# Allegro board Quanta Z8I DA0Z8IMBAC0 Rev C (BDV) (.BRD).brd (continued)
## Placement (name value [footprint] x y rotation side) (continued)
PR7100  4.75K_1%_4  [R0402]  160.57 149.01 180 top
PR7101  4.7K_NTC_4_1%  [R0402]  136.88 169.52 0 bottom
PR7102  *Short_0402  [S0402]  169.66 149.11 180 top
PR7103  *10K_1%_4  [R0402]  160.27 143.6 0 top
PR7104  10K_1%_4  [R0402]  161.16 142.56 0 top
PR7105  *Short_0402  [S0402]  150.9 159.49 180 bottom
PR7106  1_5%_6  [R0603]  156.72 158.4 90 bottom
PR7107  *Short_0402  [S0402]  155.19 161.53 0 bottom
PR7108  2.2_1%_6  [R0603]  152.99 161.75 0 bottom
PR7109  *Short_0402  [S0402]  155.78 167.52 180 bottom
PR7110  1_5%_6  [R0603]  149.61 166.96 0 bottom
PR7111  *Short_0402  [S0402]  153.78 164.1 0 bottom
PR7112  2.2_1%_6  [R0603]  155.67 162.75 180 bottom
PR7113  *Short_0402  [S0402]  163.29 133.06 90 top
PR7114  1_5%_6  [R0603]  164.85 129.92 0 bottom
PR7115  *Short_0402  [S0402]  167.42 129.57 0 top
PR7116  2.2_1%_6  [R0603]  162.72 130.86 90 top
PR8000  100K_1%_4  [R0402]  30.53 103.07 270 top
PR8001  20K_1%_2  [R0201]  52.61 200.28 180 top
PR8002  220K_1%_4  [R0402]  56.47 196.9 0 top
PR8003  20K_1%_2  [R0201]  32.46 102 180 top
PR8004  220K_1%_4  [R0402]  35.56 101.6 270 top
PR8005  10K_1%_2  [R0201]  52.96 198.8 270 top
PR8006  200K_1%_4  [R0402]  34.11 97.29 90 top
PR8007  10K_1%_2  [R0201]  34.19 102 0 top
PR8008  220K_1%_4  [R0402]  54.71 196.9 0 top
PR8009  110K_1%_4  [R0402]  36.75 101.61 90 top
PR8010  *Short_0402  [S0402]  51.06 196.67 180 top
PR8011  *0_5%_4  [R0402]  52.84 197.35 0 top
PR8012  100K_1%_4  [R0402]  48.31 199.06 90 top
PR8013  *Short_0402  [S0402]  48.29 197.33 270 top
PR8014  *Short_0402  [S0402]  32.73 97.66 180 top
PR8015  *Short_0402  [S0402]  39.48 100.3 90 top
PR8016  300K_1%_4  [R0402]  35.17 97.33 90 top
PR8017  100K_1%_4  [R0402]  38.49 100.33 270 top
PR8018  549K_1%_4  [R0402]  56.49 195.91 0 top
PR8019  *0_5%_4  [R0402]  54.74 195.91 180 top
PR8020  *Short_0402  [S0402]  53.01 195.91 0 top
PR8021  76.8K_1%_4  [R0402]  56.85 194.56 90 top
PR8022  47K_1%_4  [R0402]  25.4 103.2 270 top
PR8023  470K_5%_4  [R0402]  82.58 187.32 0 top
PR8024  47K_1%_4  [R0402]  88.72 190.49 180 top
PR8025  *1M_5%_4  [R0402]  58.83 192.86 270 top
PR8026  *Short_0402  [S0402]  57.84 192.86 90 top
PR8027  33K_1%_4  [R0402]  57.86 194.61 270 top
PR8028  220K_5%_4  [R0402]  50.7 191.59 0 top
PR8029  100K_1%_4  [R0402]  56.82 192.83 90 top
PR8030  100K_1%_4  [R0402]  83.23 190.31 90 top
PR8031  470K_5%_4  [R0402]  26.44 103.2 270 top
PR8032  470K_5%_4  [R0402]  88.72 189.5 180 top
PR8033  *Short_0402  [S0402]  24.36 116.76 90 top
PR8034  *Short_0402  [S0402]  16.84 113.9 90 top
PR8035  10K_1%_2  [R0201]  24.01 118.08 180 top
PR8036  18.7K_1%_4  [R0402]  16.48 117.34 90 top
PR8037  *0_5%_4  [R0402]  17.86 113.88 90 top
PR8038  *10K_1%_2  [R0201]  31.27 116.56 90 top
PR8039  10K_1%_4  [R0402]  17.62 118.59 270 top
PR8040  10K_1%_2  [R0201]  23.02 118.08 0 top
PR8041  *Short_0402  [S0402]  31.02 114.83 0 top
PR8042  1M_1%_2  [R0201]  25.67 113.8 0 top
PR8043  1M_1%_2  [R0201]  31.27 117.57 90 top
PR8044  510K_5%_2  [R0201]  22.33 115.47 270 top
PR8045  220K_5%_2  [R0201]  24.31 112.54 180 top
PR8046  1K_1%_2  [R0201]  25.53 115.9 90 top
PR8047  220K_5%_2  [R0201]  25.5 112.57 0 top
PR8048  *1K_1%_2  [R0201]  25.53 114.88 270 top
PR8049  *Short_0402  [S0402]  28.42 106.43 90 top
PR8050  *0_5%_4  [R0402]  30.23 106.03 90 top
PR8051  *Short_0402  [S0402]  30.87 107.39 0 top
PR8052  *Short_0402  [S0402]  35.74 114.35 180 top
PR8053  27.4K_1%_4  [R0402]  31.64 109.92 90 top
PR8054  10K_1%_2  [R0201]  33.38 114.2 0 top
PR8055  10.2K_1%_4  [R0402]  32.64 108.49 270 top
PR8056  1M_1%_2  [R0201]  24.49 111.55 90 top
PR8057  10K_1%_2  [R0201]  34.37 114.2 0 top
PR8058  *10K_1%_2  [R0201]  19.36 111.99 270 top
PR8059  1M_1%_2  [R0201]  27.03 108.56 270 top
PR8060  *Short_0402  [S0402]  18.06 111.96 180 top
PR8061  220K_5%_2  [R0201]  27.48 111.97 270 top
PR8062  220K_5%_2  [R0201]  24.49 110.54 270 top
PR8063  1K_1%_2  [R0201]  24.34 109.52 180 top
PR8064  1M_1%_2  [R0201]  19.36 110.99 270 top
PR9000  EV@1_5%_6  [R0603]  95.89 192.15 270 top
PR9001  EV@1_5%_6  [R0603]  105.08 200.05 135 top
PR9002  EV@499K_1%_4  [R0402]  98.17 194 0 top
PR9004  *EV@2.2_5%_6  [R0603]  105.11 202.92 315 bottom
PR9006  EV@1_5%_6  [R0603]  97.79 199.06 0 bottom
PR9008  *Short_0201  [S0201]  104.45 194.1 180 top
PR9009  EV@10K_1%_2  [R0201]  104.45 193.39 180 top
PR9011  EV@14.7K_1%_4  [R0402]  101.94 198.05 45 bottom
PR9013  EV@10K_1%_4  [R0402]  104.35 193.49 270 bottom
PR9014  EV@1_5%_6  [R0603]  113.59 191.59 90 bottom
PR9015  *Short_0201  [S0201]  96.93 197.41 0 top
PR9016  *Short_0402  [S0402]  96.59 198.99 180 top
PR9017  *Short_0201  [S0201]  97.86 197.52 270 top
PR9018  *EV@12K_1%_4  [R0402]  96.59 199.96 180 top
PR9019  *EV@2.2_5%_6  [R0603]  105.46 196.29 270 bottom
PR9021  EV@20.5K_1%_4  [R0402]  97.59 195.98 270 bottom
PR9022  *EV@10K_1%_4  [R0402]  98.02 198.88 90 top
PR9023  EV@6.19K_1%_4  [R0402]  97.36 196.55 180 top
PR9024  EV@4.32K_1%_4  [R0402]  95.63 196.57 0 top
PR9025  *EV@0_5%_2  [R0201]  102.16 193.95 45 bottom
PR9026  EV@100_1%_4  [R0402]  115.25 188.66 180 bottom
PR9027  EV@16.5K_1%_4  [R0402]  94.69 195.45 0 top
PR9028  *Short_0201  [S0201]  99.1 191.48 180 top
PR9029  *Short_0201  [S0201]  99.1 192.19 180 top
PR9030  EV@309_1%_4  [R0402]  93.35 195.84 90 top
PR9031  EV@100_1%_4  [R0402]  116.29 190.31 90 bottom
PR9032  EV@14.7K_1%_4  [R0402]  99.77 194.76 135 bottom
PR9033  EV@10K_1%_2  [R0201]  102.92 192.76 315 top
PR9034  *Short_0201  [S0201]  102.67 197.51 225 bottom
PR9067  *Short_0805  [S0805]  97.06 186.08 90 bottom
PR9068  *Short_0805  [S0805]  96.15 183.41 180 bottom
PR9069  *Short_0402  [S0402]  88.95 184.17 180 top
PR9070  *Short_0201  [S0201]  88.95 183.16 180 top
PR9072  *Short_0201  [S0201]  88.95 185.19 0 top
PR9073  EV@5.6_5%_8  [R0805]  95.05 192 180 bottom
PR9074  EV@100K_1%_4  [R0402]  104.42 191.54 90 bottom
PR9075  EV@10K_1%_4  [R0402]  104.04 187.87 0 bottom
PR9076  EV@10K_1%_2  [R0201]  105.85 183.79 0 bottom
PR9077  EV@1M_5%_4  [R0402]  103.46 191.54 270 bottom
PR9078  *Short_0201  [S0201]  104.7 183.79 180 bottom
PR9079  *Short_0201  [S0201]  98.69 180.99 0 bottom
PR9080  EV@47_1%_4  [R0402]  100.59 186.7 180 bottom
PR9081  EV@133_1%_4  [R0402]  99.24 186.97 90 bottom
PR9082  EV@124_1%_4  [R0402]  98.81 184.63 270 bottom
PR9085  *Short_0402  [S0402]  100 197.08 270 bottom
PR9086  EV@100K_1%_4  [R0402]  168.06 151.32 0 bottom
PR9087  EV@10_5%_6  [R0603]  167.54 158.17 0 bottom
PR9088  EV@100K_1%_2  [R0201]  167.87 157.94 180 top
PR9089  EV@2.2_5%_6  [R0603]  165.51 158.81 90 bottom
PR9090  *Short_0201  [S0201]  167.66 155.99 270 top
PR9091  *EV@0_5%_2  [R0201]  168.46 156.62 90 top
PR9092  *EV@4.7_5%_6  [R0603]  161.79 158.29 180 top
PR9093  EV@0_5%_2  [R0201]  168.71 155.75 180 top
PR9094  EV@6.49K_1%_4  [R0402]  170.41 151.3 270 bottom
PR9095  EV@2.2K_5%_4  [R0402]  168.91 155.3 180 bottom
PR9096  *EV@0_5%_4  [R0402]  169.79 153.09 0 bottom
PR9097  EV@9.31K_1%_4  [R0402]  168.44 152.7 270 bottom
PR9098  *Short_0402  [S0402]  169.78 153.08 180 top
PR9099  EV@22_5%_8  [R0805]  165.32 168.16 90 top
PR9100  EV@100K_1%_4  [R0402]  160.1 168.55 180 top
PR9101  EV@1M_5%_4  [R0402]  160.48 167.1 90 top
PR9102  EV@1M_5%_6  [R0603]  154.65 168.25 180 top
PR9103  EV@22_5%_8  [R0805]  164.14 209.6 180 top
PR9104  EV@1M_5%_6  [R0603]  155.41 170.35 270 top
PR9105  *EV@100K_1%_6  [R0603]  158.46 209.94 90 top
PR9227  22_5%_8  [R0805]  36.88 125.12 0 top
PR9244  *Short_0805  [S0805]  205.65 126.2 0 bottom
PR9245  *Short_0805  [S0805]  209.17 129.34 180 bottom
PR9248  *Short_0805  [S0805]  37.02 158.86 270 top
PR9249  *Short_0805  [S0805]  32.19 159.41 0 top
PR9255  100K_1%_2  [R0201]  37.52 145.64 270 top
PR9256  *Short_0201  [S0201]  36.5 145.56 270 top
PR9258  *Short_0201  [S0201]  135.65 130.91 90 bottom
PR9259  *Short_0201  [S0201]  136.51 126.47 180 top
PR9263  *Short_0201  [S0201]  166.84 167 90 top
PR9268  *0_5%_2  [R0201]  169.95 132.25 270 bottom
PR9269  0_5%_2  [R0201]  169.19 132.25 270 bottom
PR9270  *0_5%_2  [R0201]  60.33 182.8 90 bottom
PR9271  0_5%_2  [R0201]  61.65 187.09 180 bottom
PR9272  *0_5%_2  [R0201]  136.36 130.91 270 bottom
PR9274  *100K_NTC_4_1%  [R0402]  107.04 202.46 90 bottom
PR9275  *Short_0201  [S0201]  162.79 121.33 90 top
PR9276  *Short_0201  [S0201]  160.07 123.03 180 top
PR9277  *Short_0402  [S0402]  38.87 101.7 180 top
PR9278  *Short_0402  [S0402]  83.8 188.85 0 top
PR9279  *Short_0402  [S0402]  29.29 104.67 0 top
PR9280  *Short_0402  [S0402]  68.91 205.25 270 top
PR9281  *Short_0402  [S0402]  25.87 101.82 0 top
PU1  BQ24780SRUYR  [QFN28-4X4-4-38P]  158.29 119.35 0 bottom
PU16  G5335QT2U  [QFN23-4X4-5-25P]  143.94 125.4 270 bottom
PU3002  TMP708AIDBVR  [SOT23-2_8-95-5P-LP2985-50DBVT]  132.28 113.98 0 bottom
PU3003  JW5222RSOTB_TRPBF  [SOT23-2_8-95-6P-1_1H]  5.29 34.64 0 bottom
PU3004  JW5213DFND_TRPBF  [DFN8-2X2-5-9P-MAX8902B]  36.25 140.74 180 top
PU5000  TPS51486RJER  [QFN18-3X3-5]  73.66 183.26 180 bottom
PU6000  RT6256BGQUF  [QFN12-3X3-45-0_6H]  176.71 130.65 0 bottom
PU6001  AOZ1331ADI  [DFN14-3X2-4-15P-0_85H]  200.63 128.93 90 bottom
PU6002  AOZ1331ADI  [DFN14-3X2-4-15P-0_85H]  34.98 163.34 180 top
PU6003  RT6258CGQUF  [QFN12-3X3-45-0_6H]  55.17 183.08 180 bottom
PU7000  RT3602AJGQW  [QFN48-6X6-4-49P-EXC7900-SG11]  164.1 142.81 180 bottom
PU7001  RT9610CGQW  [DFN8-2X2-5-9P]  154.59 144.01 270 bottom
PU7002  RT9610CGQW  [DFN8-2X2-5-9P]  154.03 159.79 270 bottom
PU7003  RT9610CGQW  [DFN8-2X2-5-9P]  154.78 165.8 90 bottom
PU7004  RT9610CGQW  [DFN8-2X2-5-9P]  165.71 131.61 90 top
PU8000  AP2204K-ADJTRG1  [SOT23-2_825-95-5P]  20.32 117.7 0 top
PU8001  AP2204K-ADJTRG1  [SOT23-2_825-95-5P]  34.9 110.66 90 top
PU9000  EV@RT8813DGQW  [QFN24-4X4-5-25P-RT8813D]  101.49 195.99 225 top
PU9002  EV@AOZ1331ADI  [DFN14-3X2-4-15P-0_85H]  93.91 184.17 270 top
PU9003  EV@G9336ADJTP1U  [TSOT23-6-2_8-95-6P-1H]  101.86 184.57 0 bottom
PU9004  EV@G5335QT2U  [QFN23-4X4-5-25P]  165.03 154.41 270 bottom
Q3  2N7002KDW  [SOT363-2_1-65-6P]  121.11 111.79 180 top
Q9  EV@PJA138K  [SOT23-2-95-3P]  110.97 187.74 180 bottom
Q13  EV@PJT138K  [SC70-2_1-65-6P]  134.29 175.92 0 bottom
Q14  EV@DMG1012T-7  [SOT23-1_38-5-3P]  110.37 186.36 90 top
Q15  *EV@DMG1012T-7  [SOT23-1_38-5-3P]  105.88 182.32 180 bottom
Q16  EV@DMG1012T-7  [SOT23-1_38-5-3P]  112.35 188.85 180 top
Q19  *PJA138K  [SOT23-2-95-3P]  30.28 50.31 180 bottom
Q20  EV@DMG1012T-7  [SOT23-1_38-5-3P]  161.7 190.5 0 top
Q21  *PJA138K  [SOT23-2-95-3P]  32.38 32.64 180 bottom
Q22  2N7002KTB  [SOT23-1_38-5-3P]  76.98 102.96 180 top
Q23  DMP2130L-7  [SOT23-2-95-3P]  29.13 175.3 270 top
Q27  2N7002KDW  [SOT363-2_1-65-6P]  128.77 100.48 180 top
Q28  PMST3904  [SOT23-1_7-65-3P]  4.62 12.74 180 top
Q29  *BSS138BK  [SOT23-2_38-95-3P]  134.43 104.98 270 bottom
Q30  DMP2130L-7  [SOT23-2_38-95-3P]  216.21 122.32 180 bottom
Q31  DDTC144EUA-7-F  [SOT23-1_7-65-3P]  213.67 119.53 270 bottom
Q32  DMP2130L-7  [SOT23-2_38-95-3P]  105.81 109.79 0 bottom
Q33  *2N7002KTB  [SOT23-1_38-5-3P]  185.09 109.37 180 top
Q34  SSD@2N7002K  [SOT23-2-95-3P]  23.22 88.3 270 bottom
Q63  2N7002KTB  [SOT23-1_38-5-3P]  185.09 111.66 180 top
Q81  PJA138K  [SOT23-2-95-3P]  13.77 157.12 0 bottom
Q85  DMG301NU-7  [SOT23-2-95-3P]  108.18 108.28 90 top
Q86  METR3904-G  [SOT23-2-95-3P]  113.33 110.36 180 top
Q6508  AP2331SA-7  [SOT23-2-95-3P]  16.54 134.18 180 top
Q6509  2N7002K  [SOT23-2-95-3P]  141.84 96.9 90 top
Q6512  EV@2N7002KTB  [SOT23-1_38-5-3P]  130.48 176.04 270 bottom
Q6520  *2N7002KTB  [SOT23-1_38-5-3P]  80.2 105.15 270 top
Q6521  2N7002KDW  [SOT363-2_1-65-6P]  86.02 189.22 0 bottom
Q6522  DDTC144EUA-7-F  [SOT23-1_7-65-3P]  81.21 190.01 270 bottom
Q6523  METR3904-G  [SOT23-2-95-3P]  164.92 123.59 180 bottom
Q6531  2N7002K  [SOT23-2-95-3P]  27.87 159.66 0 top
Q6534  HDMI_CRT_P2@G5250Q1T73U  [SOT23-2_38-95-3P]  18.53 150.29 180 top
Q6535  *2N7002KDW  [SOT363-2_1-65-6P]  30.41 46.25 180 bottom
Q6539  P4@2N7002KDW  [SOT363-2_1-65-6P]  103.39 181.21 90 bottom
Q6540  P4@2N7002K  [SOT23-2-95-3P]  131.36 213.36 90 top
Q6544  METR3904-G  [SOT23-2-95-3P]  140.33 159.7 180 top
Q6548  2N7002KTB  [SOT23-1_38-5-3P]  26.85 44.35 270 bottom
Q6554  I219@2N7002KDW  [SOT363-2_1-65-6P]  10.98 163.6 90 top
Q6555  NFC_P2@2N7002KTB  [SOT23-1_38-5-3P]  59.11 94.13 90 top
Q6556  NFC_P2@2N7002KTB  [SOT23-1_38-5-3P]  63.62 95.38 270 top
Q6557  NFC_P2@2N7002KTB  [SOT23-1_38-5-3P]  65.86 95.4 90 top
Q6558  NFC_P2@2N7002KTB  [SOT23-1_38-5-3P]  68.13 95.36 270 top
Q6559  NFC_P2@2N7002KTB  [SOT23-1_38-5-3P]  61.39 94.13 90 top
Q6562  2N7002K  [SOT23-2-95-3P]  5.49 43.16 0 bottom
Q6564  2N7002KDW  [SOT363-2_1-65-6P]  92.89 182.52 270 bottom
Q6565  2N7002K  [SOT23-2-95-3P]  29.65 53.74 270 bottom
Q6566  2N7002KTB  [SOT23-1_38-5-3P]  23.22 42.74 90 bottom
Q6567  *SEN_P4@ME2N7002DKW-G  [SC88-2_1-65-6P-1_1H]  150.3 215.81 0 top
Q6568  2N7002KDW  [SOT363-2_1-65-6P]  116.18 115.09 270 top
Q6569  P4@2N7002KDW  [SOT363-2_1-65-6P]  100.94 181.47 90 bottom
Q6570  2N7002K  [SOT23-2-95-3P]  32.19 56.92 270 bottom
R1  100K_5%_4  [R0402]  119.53 114.88 0 bottom
R2  24.9_1%_4  [R0402]  126.09 146.02 270 bottom
R3  *Short_0201  [S0201]  127.85 158.23 0 top
R4  *Short_0201  [S0201]  131.1 156.34 270 top
R5  *Short_0201  [S0201]  128.3 162.73 270 top
R6  *Short_0201  [S0201]  131.6 154.72 270 top
R7  *Short_0201  [S0201]  130.86 159.97 270 top
R9  499_1%_2  [R0201]  128.58 158.65 180 bottom
R10  49.9_1%_2  [R0201]  126.14 153.72 180 bottom
R11  *1K_5%_2  [R0201]  131.37 161 180 top
R12  51_5%_2  [R0201]  129.31 163.05 180 top
R13  51_5%_2  [R0201]  126.24 159.18 180 bottom
R14  100_1%_2  [R0201]  131.9 157.22 180 top
R15  *51_5%_2  [R0201]  129.31 161.91 180 top
R16  49.9_1%_2  [R0201]  103.4 133.27 180 top
R17  *51_5%_2  [R0201]  130.13 154.8 270 top
R18  49.9_1%_2  [R0201]  109.42 133.78 180 top
R19  *51_5%_2  [R0201]  127.62 158.97 0 top
R20  49.9_1%_2  [R0201]  126.64 162.71 0 bottom
R21  49.9_1%_2  [R0201]  126.64 161.95 180 bottom
R22  100_1%_2  [R0201]  131.99 156.22 0 top
R23  1K_5%_2  [R0201]  131.09 158.09 0 bottom
R24  51_5%_2  [R0201]  129.26 159.32 0 top
R25  *51_5%_2  [R0201]  130.86 154.93 270 top
R26  470_1%_4  [R0402]  77.41 129.65 0 top
R27  *Short_0402  [S0402]  78.8 129.27 270 top
R28  121_1%_4  [R0402]  107.26 134.95 180 top
R29  80.6_1%_4  [R0402]  107.75 133.98 0 top
R30  100_1%_4  [R0402]  103.4 135.05 0 top
R31  *10K_5%_4  [R0402]  82.64 123.88 180 top
R32  *10K_5%_4  [R0402]  81.92 122.05 180 top
R33  8111K@10K_5%_4  [R0402]  89.46 134.77 0 top
R34  *1K_5%_4  [R0402]  127.43 144.51 90 bottom
R35  10K_5%_4  [R0402]  88.24 124.55 0 top
R36  4.7K_1%_2  [R0201]  89.59 127.66 90 top
R37  10K_5%_4  [R0402]  89.23 125.56 0 top
R38  100K_1%_4  [R0402]  84.13 135.02 270 top
R39  *0_5%_4  [R0402]  80.42 123.86 0 top
R40  100K_1%_4  [R0402]  84.79 122.36 0 top
R41  100K_1%_4  [R0402]  76.72 125.53 180 top
R42  1M_5%_2  [R0201]  82.15 104.9 90 top
R43  10K_1%_2  [R0201]  118.08 117.9 270 bottom
R44  4.7K_5%_2  [R0201]  106.82 131.35 0 top
R45  10K_5%_4  [R0402]  83.79 127.08 0 top
R46  10K_5%_4  [R0402]  81.64 126.04 180 top
R47  *Short_0402  [S0402]  80.06 126.94 270 top
R51  *0_5%_4  [R0402]  78.57 126.59 0 top
R56  100K_1%_4  [R0402]  84.38 101.68 0 top
R59  10K_5%_4  [R0402]  87.68 113.56 180 top
R60  10K_5%_4  [R0402]  118.94 117.82 0 top
R61  *HDMI_CRT_P2@Short_4  [S0402]  35.5 146.64 270 top
R63  56.2_1%_4  [R0402]  131.17 156.15 180 bottom
R64  220_1%_4  [R0402]  129.03 156.18 180 bottom
R65  *54.9/F_4  [R0402]  131.17 157.11 0 bottom
R66  *Short_0402  [S0402]  126.83 155.16 90 bottom
R67  100_1%_4  [R0402]  129.06 157.7 0 bottom
R68  *Short_0402  [S0402]  127.28 156.64 0 bottom
R69  *Short_4  [S0402]  127.96 139.94 0 bottom
R70  *Short_6  [S0603]  134.43 130.55 90 top
R71  *Short_6  [S0603]  89.8 140.06 90 top
R72  100_1%_2  [R0201]  105.92 133.85 90 top
R73  HDMI_CRT_P2@10K_5%_4  [R0402]  95.81 119.55 90 bottom
R74  100_1%_2  [R0201]  104.95 133.85 90 top
R77  *Short_0805  [S0805]  114.16 147.3 270 top
R78  *Short_0805  [S0805]  112.18 147.3 270 top
R79  *0.0002_5%_0805  [R0805]  110.06 153.17 90 top
R80  *Short_0805  [S0805]  110.21 147.3 270 top
R81  *0.0002_5%_0805  [R0805]  112.03 153.17 90 top
R82  49.9_1%_2  [R0201]  131.46 153.84 0 top
R83  *1K_5%_2  [R0201]  130.33 159.72 270 bottom
R84  *Short_0402  [S0402]  88.19 130.2 180 top
R85  *0_5%_4  [R0402]  126.52 163.62 0 bottom
R86  *1K_5%_2  [R0201]  126.64 160.07 0 bottom
R87  1K_5%_2  [R0201]  126.64 161.08 0 bottom
R88  *100K_1%_4  [R0402]  92.46 110.76 0 top
R89  4.7K_5%_2  [R0201]  82.26 122.94 180 top
R90  *20K_1%_2  [R0201]  87.41 123.09 0 top
R91  22_1%_4  [R0402]  96.17 127.58 0 bottom
R92  22_1%_4  [R0402]  96.96 124.47 90 bottom
R94  *10K_1%_2  [R0201]  107.87 113.49 0 bottom
R95  2.2K_5%_2  [R0201]  122.34 115.26 0 top
R96  8.2K_1%_2  [R0201]  106.47 110.87 270 top
R97  2.2K_5%_2  [R0201]  121.31 114.86 180 top
R98  *10K_1%_2  [R0201]  108.33 114.27 180 bottom
R100  10K_5%_4  [R0402]  107.45 110.87 90 top
R102  10K_1%_2  [R0201]  108.33 115.03 180 bottom
R103  2.2K_5%_2  [R0201]  115.21 118.03 180 bottom
R104  2.2K_5%_2  [R0201]  114.13 115.24 90 bottom
R106  33.2_1%_4  [R0402]  132.95 109.38 90 bottom
R107  100K_1%_4  [R0402]  117.86 106.55 90 bottom
R108  33.2_1%_4  [R0402]  134.67 108.4 180 bottom
R109  33.2_1%_4  [R0402]  116.49 106.55 180 bottom
R110  33.2_1%_4  [R0402]  120.17 98.9 270 bottom
R111  33.2_1%_4  [R0402]  116.84 104.47 270 bottom
R112  100K_1%_4  [R0402]  121.31 100.12 270 bottom
R114  4.7K_5%_2  [R0201]  118.23 110.22 270 top
R115  4.7K_5%_2  [R0201]  119.26 111.77 90 top
R116  *20K_1%_2  [R0201]  95.05 124.33 90 bottom
R117  *4.7K_5%_2  [R0201]  81.73 131.68 270 top
R118  1K_5%_2  [R0201]  80.84 131.56 0 top
R119  4.7K_5%_2  [R0201]  113.27 116.95 270 bottom
R120  *4.7K_5%_2  [R0201]  83.36 117.25 90 top
R121  *20K_1%_2  [R0201]  113.27 117.95 90 bottom
R122  10K_5%_4  [R0402]  90.02 116.81 90 top
R123  *10K_5%_4  [R0402]  114.67 118.42 90 top
R124  *20K_1%_2  [R0201]  86.84 121.36 0 top
R125  20K_1%_2  [R0201]  114.43 120.92 135 top
R126  2.2K_5%_4  [R0402]  94.97 106.55 0 top
R134  *10K_5%_4  [R0402]  118.83 114.7 270 top
R135  *2.2K_1%_2  [R0201]  17.99 53.39 0 bottom
R136  113_1%_4  [R0402]  120.93 127.05 180 top
R137  1K_5%_2  [R0201]  121.47 124.79 270 top
R138  1K_5%_2  [R0201]  122.07 125.75 0 top
R139  100_1%_2  [R0201]  120.5 125.7 180 top
R144  4.7K_5%_2  [R0201]  104.54 112.63 270 bottom
R145  60.4_1%_2  [R0201]  127.15 117.01 0 bottom
R146  150_1%_2  [R0201]  100.82 109.71 90 top
R147  200_1%_2  [R0201]  115.77 122.4 90 top
R148  10K_5%_4  [R0402]  122.71 121.84 90 top
R152  100K_5%_4  [R0402]  84.84 123.6 0 top
R153  *100K_5%_4  [R0402]  122.48 116.5 180 top
R154  10K_5%_4  [R0402]  86.11 117.48 0 top
R155  10K_5%_4  [R0402]  89.28 119.5 90 top
R157  *20K_1%_2  [R0201]  86.11 123.59 90 top
R158  100K_5%_4  [R0402]  119.03 121.25 0 top
R159  10K_5%_4  [R0402]  82.76 119.78 270 top
R160  10K_1%_2  [R0201]  19.49 58.57 180 bottom
R161  *0_5%_4  [R0402]  103.28 111.88 0 bottom
R166  33.2_1%_4  [R0402]  124.36 117.52 90 bottom
R167  1M_5%_4  [R0402]  124.87 116.18 180 bottom
R168  33.2_1%_4  [R0402]  125.32 117.52 90 bottom
R169  10M_5%_4  [R0402]  103.4 117.78 180 bottom
R178  20K_1%_4  [R0402]  19.54 64.57 90 top
R179  10K_5%_4  [R0402]  104.85 109.5 0 top
R180  20K_1%_2  [R0201]  194.24 116.23 180 bottom
R183  *4.7K_5%_2  [R0201]  129.59 113.56 270 top
R186  *1K_5%_2  [R0201]  86.06 132.36 270 top
R187  33_5%_2  [R0201]  91.21 130.83 0 top
R188  33_5%_2  [R0201]  83.7 132.25 0 top
R191  33_5%_2  [R0201]  24.13 32.13 0 bottom
R194  33_5%_2  [R0201]  84.1 133.4 0 top
R197  4.7K_5%_4  [R0402]  27.36 54.38 270 bottom
R205  10K_1%_2  [R0201]  26.61 50.98 0 bottom
R206  100K_1%_2  [R0201]  26.61 52.51 0 bottom
R208  100K_1%_2  [R0201]  14.02 68.15 0 top
R209  200_1%_2  [R0201]  89.59 115.18 180 top
R210  *Short_0402  [S0402]  90.96 110.33 90 top
R211  *Short_0402  [S0402]  107.8 116.94 180 bottom
R212  *0_5%_4  [R0402]  113.86 112.61 180 top
R213  *Short_0402  [S0402]  111.34 115.49 0 top
R215  *100K_5%_4  [R0402]  96.37 106.74 270 bottom
R216  *1K_5%_2  [R0201]  128.39 156.27 0 top
R217  *1K_5%_2  [R0201]  127.31 162.43 0 top
R220  *1K_5%_2  [R0201]  119.21 98.78 270 bottom
R221  *1K_5%_2  [R0201]  117.91 101.44 180 bottom
R222  *1.5K_5%_4  [R0402]  119.79 100.5 0 bottom
R224  240_1%_2  [R0201]  46.61 138.49 270 top
R225  *0_5%_4  [R0402]  44.63 108.23 180 top
R226  *0_5%_4  [R0402]  44.63 106.19 180 top
R227  *0_5%_4  [R0402]  44.17 128.11 180 top
R228  *Short_0402  [S0402]  44.63 107.21 0 top
R229  *Short_0402  [S0402]  44.63 105.18 180 top
R230  *Short_0402  [S0402]  44.51 129.48 270 top
R231  240_1%_2  [R0201]  49.41 148.48 180 top
R232  240_1%_2  [R0201]  49.42 147.74 180 top
R233  240_1%_2  [R0201]  46.68 149.02 180 top
R234  240_1%_2  [R0201]  49.4 149.97 0 top
R235  240_1%_2  [R0201]  51.8 147.25 180 top
R236  240_1%_2  [R0201]  51.85 145.85 180 top
R237  240_1%_2  [R0201]  46.68 149.78 180 top
R238  240_1%_2  [R0201]  49.42 149.22 0 top
R239  240_1%_2  [R0201]  47.22 146.79 180 top
R240  240_1%_2  [R0201]  47.22 145.99 180 top
R241  1K_1%_4  [R0402]  45.48 124.37 0 top
R242  2_1%_6  [R0603]  44.75 121.87 270 top
R243  1K_1%_4  [R0402]  45.52 126.05 180 top
R244  24.9_1%_4  [R0402]  46.02 119.61 270 top
R296  *EV@Short_4  [S0402]  117.85 207.64 90 bottom
R297  EV@10K_1%_4  [R0402]  110.69 184.99 90 bottom
R299  *EV@Short_4  [S0402]  126.31 198.36 90 top
R305  *EV@Short_4  [S0402]  108.38 181.51 90 bottom
R306  EV@100K_1%_4  [R0402]  108.32 180.06 180 bottom
R307  *EV@200_1%_2  [R0201]  140.74 207.26 180 bottom
R310  4.7K_5%_4  [R0402]  7.04 13.51 0 top
R311  EV@10K_1%_4  [R0402]  118.94 207.65 270 bottom
R312  EV@2.49K_1%_4  [R0402]  142.14 207.64 90 bottom
R313  EV@10K_1%_4  [R0402]  115.98 187.57 0 bottom
R314  EV@10K_1%_4  [R0402]  144.68 189.86 270 bottom
R315  EV@10K_1%_4  [R0402]  145.06 188.46 0 bottom
R316  EV@10K_1%_4  [R0402]  145.82 187.45 0 bottom
R317  EV@10K_1%_4  [R0402]  158.17 205.23 0 top
R318  EV@40.2_1%_4  [R0402]  146.87 181.56 0 top
R319  EV@40.2_1%_4  [R0402]  145.91 182.97 90 top
R320  EV@60.4_1%_2  [R0201]  145.97 183.51 0 bottom
R321  *EV@60.4_1%_2  [R0201]  135.91 186.63 0 top
R322  *EV@60.4_1%_2  [R0201]  136.25 189.43 270 top
R323  *EV@0_5%_4  [R0402]  120.74 209.15 180 bottom
R324  *EV@Short_4  [S0402]  120.74 210.16 180 bottom
R325  EV@100K_1%_4  [R0402]  125.37 208.47 270 bottom
R326  EV@10K_5%_4  [R0402]  117.09 178.43 90 bottom
R329  *EV@Short_4  [S0402]  124.17 192.21 270 top
R330  *EV@10K_1%_4  [R0402]  123.12 176.43 90 bottom
R331  EV@10K_1%_4  [R0402]  124.13 178.46 90 bottom
R332  EV@10K_1%_4  [R0402]  123.12 178.46 90 bottom
R339  *EV@Short_4  [S0402]  134.47 178.23 0 bottom
R341  EV@100K_5%_4  [R0402]  130.96 178.23 180 bottom
R342  EV@100K_5%_4  [R0402]  129.18 178.23 0 bottom
R343  EV@100K_5%_4  [R0402]  132.74 178.23 180 bottom
R344  EV@100K_5%_4  [R0402]  113.69 186.05 0 bottom
R345  EV@100K_5%_4  [R0402]  113.69 185.03 0 bottom
R346  EV@100K_5%_4  [R0402]  113.69 183 0 bottom
R347  *EV@100K_5%_4  [R0402]  113.69 187.07 0 bottom
R348  *EV@100K_5%_4  [R0402]  113.69 181.99 0 bottom
R349  *EV@100K_5%_4  [R0402]  113.69 184.02 0 bottom
R350  *EV@30.1K_1%_4  [R0402]  130.96 179.19 0 bottom
R351  *EV@100K_5%_4  [R0402]  132.74 179.19 180 bottom
R352  EV@100K_5%_4  [R0402]  129.18 179.19 180 bottom
R353  EV@100K_5%_4  [R0402]  115.98 185.54 180 bottom
R354  EV@100K_5%_4  [R0402]  115.98 184.4 0 bottom
R355  EV@100K_5%_4  [R0402]  115.98 182.37 180 bottom
R356  EV@100K_5%_4  [R0402]  115.98 186.56 180 bottom
R357  EV@100K_5%_4  [R0402]  115.98 181.37 180 bottom
R358  EV@100K_5%_4  [R0402]  115.98 183.38 180 bottom
R359  *0_5%_4  [R0402]  171.07 115.44 270 top
R361  4.7K_5%_2  [R0201]  161.79 113.17 90 top
R362  EV@4.7K_5%_2  [R0201]  136.71 175.44 180 bottom
R363  EV@2.2K_5%_2  [R0201]  121.92 178.43 270 bottom
R364  *EV@Short_4  [S0402]  122.1 176.43 90 bottom
R365  EV@4.7K_5%_2  [R0201]  132 175.31 270 bottom
R366  EV@2.2K_5%_2  [R0201]  120.95 178.43 270 bottom
R367  EV@2.2K_5%_2  [R0201]  119.99 178.43 270 bottom
R368  EV@2.2K_5%_2  [R0201]  119.02 178.43 270 bottom
R369  4.7K_5%_2  [R0201]  161.03 113.17 90 top
R370  *EV@Short_4  [S0402]  115.72 179.37 0 bottom
R372  *EV@Short_4  [S0402]  114.56 186.34 0 top
R373  *EV@Short_4  [S0402]  113.58 182.96 0 top
R374  *EV@Short_4  [S0402]  111.04 179.83 0 top
R375  *0_5%_4  [R0402]  23.86 65.86 270 bottom
R376  *EV@Short_4  [S0402]  115.72 180.34 0 bottom
R378  *EV@10K_1%_4  [R0402]  128.83 176.81 270 bottom
R380  43_5%_4  [R0402]  158.99 113.56 180 top
R382  *EV@0_5%_4  [R0402]  108.84 177.65 180 bottom
R383  4.7K_5%_2  [R0201]  147.63 109.9 0 top
R384  *EV@Short_4  [S0402]  108.33 179.08 0 bottom
R385  *EV@4.7K_5%_2  [R0201]  107.62 183.28 0 bottom
R386  EV@10K_5%_4  [R0402]  112.34 185.83 180 top
R391  EV@10K_1%_4  [R0402]  113.44 179.98 0 bottom
R394  EV@10K_1%_4  [R0402]  114.11 187.77 90 top
R395  EV@10K_1%_4  [R0402]  115.72 178.41 0 bottom
R396  EV@10K_1%_4  [R0402]  115.24 205.84 0 bottom
R397  EV@10K_1%_4  [R0402]  112.81 180.77 0 top
R398  EV@100K_1%_4  [R0402]  124.19 187.15 90 top
R399  *EV@10K_1%_4  [R0402]  113.69 178.94 0 bottom
R402  *22_5%_4  [R0402]  147.86 104.31 180 top
R403  EV@10K_1%_4  [R0402]  110.69 180.83 180 top
R404  EV@10K_1%_4  [R0402]  113.69 180.97 0 bottom
R405  EV@120_1%_4  [R0402]  158.27 187.07 90 bottom
R406  EV@120_1%_4  [R0402]  157.89 191.77 180 bottom
R407  EV@549_1%_4  [R0402]  159.41 189.48 0 top
R409  100K_1%_4  [R0402]  78.57 104.64 90 top
R410  EV@1.33K_1%_4  [R0402]  159.41 188.46 0 top
R411  EV@931_1%_4  [R0402]  159.41 190.5 0 top
R414  20K_1%_2  [R0201]  25.34 100.44 180 top
R415  39K_1%_4  [R0402]  23.24 97.56 270 top
R416  100K_5%_4  [R0402]  17.94 100.96 270 top
R417  10K_5%_4  [R0402]  15.62 97.58 90 top
R418  10K_5%_4  [R0402]  15.68 98.98 180 top
R421  *Short_0402  [S0402]  20.06 89.67 180 top
R422  *Short_0402  [S0402]  20.06 90.82 180 top
R424  *Short_0402  [S0402]  21.82 91.79 180 top
R425  *Short_0402  [S0402]  17.3 103.45 180 top
R426  *Short_0402  [S0402]  17.3 104.52 180 top
R427  *Short_0402  [S0402]  22.44 105.2 180 top
R428  *Short_0402  [S0402]  22.44 106.35 180 top
R429  *Short_0402  [S0402]  23.73 107.36 180 top
R430  *Short_0402  [S0402]  23.73 108.51 180 top
R432  *Short_0402  [S0402]  21.82 92.93 180 top
R436  *Short_4  [S0402]  69.41 187.79 180 bottom
R439  *1K_5%_2  [R0201]  64.11 188.19 270 bottom
R440  *1K_5%_2  [R0201]  82.88 192.09 270 bottom
R441  1K_1%_4  [R0402]  65.99 188.49 270 bottom
R442  100K_1%_4  [R0402]  67.01 188.49 270 bottom
R443  10_5%_2  [R0201]  64.98 188.19 270 bottom
R445  *Short_4  [S0402]  77.98 194.72 180 top
R446  100K_1%_4  [R0402]  77.78 193.7 0 top
R447  100K_5%_4  [R0402]  16.67 27.36 0 top
R449  *Short_4  [S0402]  12.5 38.72 270 bottom
R450  *Short_0603  [S0603]  18.32 25.54 90 bottom
R451  200K_1%_4  [R0402]  22.41 27.33 90 bottom
R452  100K_5%_4  [R0402]  23.8 27.71 180 bottom
R454  *0_5%_4  [R0402]  23.68 37.49 90 bottom
R455  *Short_0603  [S0603]  26.48 39.21 0 bottom
R458  *HDMI_CRT_P2@4.7K_5%_4  [R0402]  31.3 148.1 270 top
R459  *Short_4  [S0402]  28.75 36.97 180 bottom
R460  *Short_4  [S0402]  31 28.53 0 bottom
R461  22_5%_2  [R0201]  25.73 34 180 bottom
R462  *0_5%_4  [R0402]  31.42 29.99 270 bottom
R463  *Short_4  [S0402]  13.62 38.72 90 bottom
R464  *0_5%_4  [R0402]  18.59 18.81 135 bottom
R465  *0_5%_4  [R0402]  21.01 21.04 135 top
R467  *Short_4  [S0402]  11.92 34.38 180 bottom
R468  2.2K_5%_2  [R0201]  19.13 25.12 90 top
R469  *0_5%_4  [R0402]  16.13 36.58 90 bottom
R470  *Short_4  [S0402]  18.59 18.81 315 top
R471  2.2K_5%_2  [R0201]  19.87 25.12 90 top
R472  62_1%_4  [R0402]  15.27 21.56 180 bottom
R473  62_1%_4  [R0402]  10.28 28.48 270 bottom
R474  *10K_5%_4  [R0402]  16.64 21.21 90 bottom
R475  *10K_5%_4  [R0402]  17.66 22.14 90 bottom
R476  4.7K_5%_2  [R0201]  16.51 22.62 270 bottom
R477  4.7K_5%_2  [R0201]  17.79 23.39 180 bottom
R478  1K_5%_2  [R0201]  22.6 37.1 90 bottom
R479  *10K_5%_4  [R0402]  32.44 29.99 270 bottom
R484  *150_1%_4  [R0402]  15.67 121.4 270 top
R486  *150_1%_4  [R0402]  16.16 125.05 270 top
R487  *150_1%_4  [R0402]  15.7 126.7 270 bottom
R489  *150_1%_4  [R0402]  16.15 128.32 270 top
R490  2.2K_5%_2  [R0201]  16.56 131.64 270 top
R491  2.2K_5%_2  [R0201]  15.86 130.06 90 top
R494  2.2K_5%_2  [R0201]  30.96 124.34 0 top
R495  *HDD_R@4.7K_5%_2  [R0201]  234.88 116.35 0 top
R497  HDD_R@4.7K_5%_2  [R0201]  233.35 115.08 180 top
R498  *HDD_R@4.7K_5%_2  [R0201]  234.88 115.08 0 top
R499  *HDD_R@4.7K_5%_2  [R0201]  233.35 114.27 180 top
R500  HDD_R@4.7K_5%_2  [R0201]  234.88 114.27 0 top
R502  2.2K_5%_2  [R0201]  32.65 122.17 180 top
R503  *HDD_R@4.7K_5%_2  [R0201]  224.67 114.8 180 top
R504  HDD_R@4.7K_5%_2  [R0201]  226.19 115.74 0 top
R505  *HDD_R@4.7K_5%_2  [R0201]  224.67 115.74 180 top
R506  *HDD_R@4.7K_5%_2  [R0201]  226.19 117.67 0 top
R507  HDMI_R_P4@10.5K_1%_4  [R0402]  23.71 146.3 270 top
R509  8111K@1K_5%_2  [R0201]  28.88 162.96 180 top
R510  8111K@15K_1%_4  [R0402]  24.18 162.2 270 top
R511  *Short_4  [S0402]  28.88 169.06 180 top
R512  *Short_4  [S0402]  28.88 170.08 180 top
R516  75_1%_8  [R0805]  37.65 184.93 270 top
R517  75_1%_8  [R0805]  35.36 184.93 270 top
R518  75_1%_8  [R0805]  32.06 184.93 270 top
R519  75_1%_8  [R0805]  29.77 184.93 270 top
R551  *10K_1%_2  [R0201]  120.43 114.98 90 top
R554  *10K_5%_4  [R0402]  119.35 116.23 270 bottom
R558  *Short_4  [S0402]  131.2 100.71 270 top
R559  4.7K_5%_2  [R0201]  126.71 99.63 180 top
R560  *Short_4  [S0402]  126.27 100.88 0 top
R562  4.7K_5%_2  [R0201]  130.27 99.06 0 top
R566  4.7K_5%_2  [R0201]  135.14 97.6 90 top
R567  4.7K_5%_2  [R0201]  129.81 96.19 180 top
R572  *Short_4  [S0402]  125.74 96.65 90 top
R573  *Short_4  [S0402]  134.76 107.4 0 bottom
R574  *10K_5%_4  [R0402]  126.75 96.65 270 top
R575  *Short_8  [S0805]  170.96 111.62 0 bottom
R576  1K_5%_2  [R0201]  166.52 124.71 90 bottom
R579  10K_5%_4  [R0402]  213.29 121.69 180 bottom
R580  10K_1%_2  [R0201]  82.43 101.16 180 top
R583  10K_1%_2  [R0201]  81.72 95.53 180 top
R586  10K_1%_2  [R0201]  81.28 99.86 0 top
R588  *0_5%_4  [R0402]  23.05 25.17 135 top
R589  *0_5%_4  [R0402]  17.06 17.37 135 top
R592  *0_5%_2  [R0201]  83.24 94.76 0 top
R593  *Short_2  [S0201]  83.52 99.72 0 top
R596  33_5%_2  [R0201]  82.37 99.78 0 top
R597  33_5%_2  [R0201]  83.24 97.81 0 top
R598  33_5%_2  [R0201]  83.24 95.53 0 top
R599  *Short_2  [S0201]  81.28 99.13 0 top
R600  *1.2K_5%_2  [R0201]  91.88 97.81 180 top
R601  *Short_2  [S0201]  83.62 100.53 0 top
R604  *49.9K_1%_2  [R0201]  115.82 112.32 0 bottom
R605  *49.9K_1%_4  [R0402]  117 116.19 270 bottom
R606  *49.9K_1%_4  [R0402]  117.17 114.45 90 bottom
R607  *49.9K_1%_2  [R0201]  116.87 117.9 270 bottom
R608  *0_5%_4  [R0402]  104.05 107.75 270 bottom
R609  10K_1%_2  [R0201]  108.65 110.19 180 bottom
R614  *Short_4  [S0402]  100.36 107.46 180 bottom
R645  *SSD@Short_2  [S0201]  22.84 73.8 90 top
R646  *SSD@Short_2  [S0201]  21.93 82.6 270 bottom
R647  *SSD@Short_2  [S0201]  22.7 82.6 270 bottom
R648  *SSD@Short_2  [S0201]  24.79 73.17 0 top
R649  SSD@100K_1%_4  [R0402]  18 82.3 0 bottom
R651  4.7K_5%_2  [R0201]  183.44 109.37 90 top
R652  *4.7K_5%_2  [R0201]  183.44 111.66 90 top
R653  *SSD@Short_2  [S0201]  22.04 90.68 270 bottom
R654  *SSD@0_5%_2  [R0201]  17.36 85.88 90 bottom
R655  *0_5%_4  [R0402]  198.31 106.74 90 bottom
R662  *CNV@20K_1%_2  [R0201]  127.62 112.18 0 top
R663  *CNV@20K_1%_2  [R0201]  127.62 111.42 0 top
R664  *CNV@20K_1%_2  [R0201]  194.24 114.45 180 bottom
R665  CNV@22_5%_2  [R0201]  194.19 117.09 0 bottom
R666  CNV@33_5%_2  [R0201]  129.72 112.67 180 top
R667  CNV@22_5%_2  [R0201]  194.24 115.34 0 bottom
R668  CNV@33_5%_2  [R0201]  130.83 112.68 180 top
R670  *Short_4  [S0402]  194.24 113.43 180 bottom
R671  *10K_1%_2  [R0201]  194.24 111.78 0 bottom
R672  *10K_1%_2  [R0201]  195.7 111.2 90 bottom
R673  *Short_2  [S0201]  194.23 110.85 0 bottom
R674  *Short_2  [S0201]  194.23 110.09 0 bottom
R675  *Short_2  [S0201]  194.23 109.33 0 bottom
R676  *CNV@75K_1%_4  [R0402]  188.4 119.02 0 top
R677  CNV@75K_1%_2  [R0201]  188.37 114.2 0 top
R678  *CNV@75K_1%_4  [R0402]  185.86 119.02 0 top
R679  CNV@71.5K_1%_4  [R0402]  185.86 114.2 0 top
R720  33_5%_2  [R0201]  194 98.94 270 top
R732  *100K_5%_4  [R0402]  28.63 34.82 180 bottom
R734  10K_1%_2  [R0201]  25.89 28.49 0 bottom
R735  *Short_2  [S0201]  25.81 24.1 0 bottom
R736  *Short_4  [S0402]  23.78 26.5 0 top
R738  *Short_4  [S0402]  26.47 30.38 0 bottom
R746  *HDMI_R_P4@10K_5%_4  [R0402]  20.4 148.17 270 top
R747  *HDMI_R_P4@10K_5%_4  [R0402]  24.64 148.13 180 top
R748  HDMI_R_P4@0_5%_4  [R0402]  24.72 146.3 270 top
R749  HDMI_R_P4@0_5%_4  [R0402]  20.4 146.31 270 top
R752  6.2K_1%_4  [R0402]  23.19 63.18 180 bottom
R753  *Short_6  [S0603]  26.14 65.91 180 bottom
R754  HDMI_CRT_P2@4.7K_5%_4  [R0402]  34.64 124.99 90 top
R755  HDMI_CRT_P2@4.7K_5%_4  [R0402]  32.98 126.38 90 top
R756  HDMI_CRT_P2@4.7K_5%_4  [R0402]  20.78 120.29 90 top
R757  *HDMI_CRT_P2@4.7K_5%_4  [R0402]  21.8 120.29 270 top
R758  *HDMI_CRT_P2@4.7K_5%_4  [R0402]  19.8 120.61 90 top
R759  *HDMI_CRT_P2@4.7K_5%_4  [R0402]  18.7 120.6 270 top
R760  *HDMI_CRT_P2@4.7K_5%_4  [R0402]  32.44 131.16 180 top
R761  *HDMI_CRT_P2@4.7K_5%_4  [R0402]  30.69 130.79 0 top
R762  *HDMI_CRT_P2@4.7K_5%_4  [R0402]  30.89 134.25 180 top
R763  *HDMI_CRT_P2@4.7K_5%_4  [R0402]  30.89 133.24 0 top
R764  HDMI_CRT_P2@4.7K_5%_4  [R0402]  33.52 118.35 90 top
R765  *HDMI_CRT_P2@4.7K_5%_4  [R0402]  30.86 120.66 0 top
R770  HDMI_CRT_P2@100K_5%_4  [R0402]  31.17 128.42 0 top
R772  *HDMI_CRT_P2@Short_6  [S0603]  33.95 128.58 270 top
R773  HDMI_CRT_P2@1M_5%_4  [R0402]  29.05 119.94 90 top
R779  HDMI_CRT_P2@4.99K_1%_4  [R0402]  17.63 120.37 270 top
R803  HDMI_CRT_P2@75_1%_4  [R0402]  24.57 151.09 0 top
R821  1K/F_4  [R0402]  110.8 111.74 0 top
R822  1K/F_4  [R0402]  110.9 107.35 0 top
R825  *100K_1%_4  [R0402]  108.95 111.27 90 top
R830  *HDMI_CRT_P2@10K_5%_4  [R0402]  32.62 132.71 270 top
R832  *HDMI_CRT_P2@100K_1%_4  [R0402]  30.89 132.22 0 top
R842  *HDMI_CRT_P2@4.7K_5%_4  [R0402]  23.8 120.47 90 top
R843  *HDMI_CRT_P2@4.7K_5%_4  [R0402]  32.5 118.35 90 top
R844  *HDMI_CRT_P2@4.7K_5%_4  [R0402]  22.78 120.47 270 top
R845  *HDMI_CRT_P2@4.7K_5%_4  [R0402]  31.05 119.36 180 top
R849  HDMI_CRT_P2@75_1%_4  [R0402]  23.62 152.49 90 top
R850  HDMI_CRT_P2@75_1%_4  [R0402]  23.37 154.31 180 top
R890  100K_5%_2  [R0201]  149.03 95.78 180 top
R894  *Short_2  [S0201]  147.98 100.63 180 top
R895  33_5%_2  [R0201]  169.12 113.39 0 top
R953  1K_1%_4  [R0402]  78.89 95.11 180 top
R956  33_5%_2  [R0201]  170.51 104.01 270 top
R960  33_5%_2  [R0201]  169.01 104.9 0 top
R971  20K_1%_2  [R0201]  81.74 106.47 90 top
R978  *Short_4  [S0402]  76.33 96.56 270 top
R979  20K_1%_2  [R0201]  82.15 103.86 270 top
R1234  HDD_R@4.7K_5%_2  [R0201]  233.35 116.35 180 top
R1235  HDD_R@4.7K_5%_2  [R0201]  226.19 114.8 0 top
R1236  *HDD_R@4.7K_5%_2  [R0201]  226.19 116.68 0 top
R1237  HDD_R@4.7K_5%_2  [R0201]  224.67 117.67 180 top
R1238  HDD_R@4.7K_5%_2  [R0201]  224.67 116.68 180 top
R1239  *HDD_R@Short_4  [S0402]  234.9 118.13 90 top
R1250  20K_1%_2  [R0201]  16.02 134.72 0 bottom
R1251  *Short_8  [S0805]  110.86 114.87 270 bottom
R1252  *20K_1%_2  [R0201]  103.66 110.93 0 bottom
R1253  *Short_6  [S0603]  122.45 116.73 0 bottom
R1260  *Short_0402  [S0402]  125.5 121.46 180 top
R1262  *Short_0402  [S0402]  128.36 124.86 180 bottom
R1264  *Short_0402  [S0402]  128.37 123.84 180 bottom
R1265  *Short_0402  [S0402]  128.02 130.59 0 top
R1266  *Short_0402  [S0402]  128.04 128.67 0 top
R1267  *Short_0402  [S0402]  125.7 115.18 180 top
R1270  *Short_0402  [S0402]  109.97 117.39 90 top
R1271  *Short_0402  [S0402]  128.04 129.63 0 top
R1272  *Short_0603  [S0603]  122.45 115.16 180 bottom
R1273  *Short_0402  [S0402]  112.72 114.99 180 bottom
R1274  *Short_0402  [S0402]  112.72 115.97 180 bottom
R1275  *Short_8  [S0805]  128.44 122 0 bottom
R1276  *Short_4  [S0402]  110.99 116.88 270 top
R1277  *Short_6  [S0603]  130.56 116.38 0 bottom
R1278  *Short_4  [S0402]  113.68 117.69 270 top
R1279  *Short_4  [S0402]  128.55 122.48 180 top
R1280  *Short_4  [S0402]  126.26 130.83 0 top
R1281  *Short_4  [S0402]  93.84 109.14 270 top
R1616  *HDMI_CRT_P2@4.7_5%_4  [R0402]  30.28 148.1 270 top
R2228  60.4_1%_4  [R0402]  129.5 138.54 90 bottom
R2229  1K_5%_4  [R0402]  130.51 138.52 270 bottom
R2257  *Short_2  [S0201]  91.67 106.54 0 top
R2525  *Short_8  [S0805]  128.43 119 0 bottom
R2652  *SSD@Short_2  [S0201]  34.08 82.57 270 bottom
R2653  *SSD@Short_2  [S0201]  33.31 82.57 270 bottom
R2654  *SSD@Short_2  [S0201]  30.55 82.55 270 bottom
R2655  *SSD@Short_2  [S0201]  29.78 82.55 270 bottom
R2656  *SSD@Short_2  [S0201]  26.99 82.55 270 bottom
R2657  *SSD@Short_2  [S0201]  26.25 82.55 270 bottom
R2658  *SSD@Short_2  [S0201]  19.22 83.51 270 bottom
R2659  *SSD@Short_2  [S0201]  18.45 83.51 270 bottom
R2660  *SSD@100K_5%_4  [R0402]  23.73 73.8 270 top
R2661  *SSD@Short_8  [S0805]  27.74 68.86 0 bottom
R2662  *Short_2  [S0201]  194.22 107.88 0 bottom
R2663  *Short_2  [S0201]  194.22 107.11 0 bottom
R2664  *Short_2  [S0201]  194.21 106.38 0 bottom
R2665  *Short_2  [S0201]  194.24 112.54 0 bottom
R2666  *CNV_N@0_5%_8  [R0805]  195.89 120.04 90 bottom
R2667  *CNV@Short_8  [S0805]  193.86 120.04 90 bottom
R4008  I219@1K_1%_4  [R0402]  12.98 166.87 0 top
R4009  I219@3.01K_1%_4  [R0402]  25.7 171.74 180 top
R4023  I219@499_1%_4  [R0402]  14.3 168.97 180 top
R4024  I219@499_1%_4  [R0402]  12.99 165.87 0 top
R9261  *Short_8  [S0805]  137.16 131.44 0 top
R9340  I219@4.7K_1%_4  [R0402]  28.88 163.85 180 top
R10880  *10K_1%_2  [R0201]  119.68 114.99 90 top
R25270  *100K_1%_4  [R0402]  67.57 190.75 90 top
R25271  *100K_1%_4  [R0402]  66.55 190.75 90 top
R25282  EV@1.33K_1%_4  [R0402]  158.14 193.82 180 top
R25283  EV@931_1%_4  [R0402]  159.92 192.53 0 top
R25284  EV@549_1%_4  [R0402]  159.92 193.8 0 top
R25288  *Short_4  [S0402]  58.98 190.78 270 bottom
R25289  *Short_4  [S0402]  60 190.78 270 bottom
R25292  *Short_4  [S0402]  12.25 61.02 0 bottom
R25295  *Short_4  [S0402]  110.05 107.65 180 bottom
R25297  *Short_4  [S0402]  16.02 132.81 0 bottom
R25298  100K_5%_4  [R0402]  144.5 96.85 0 top
R25300  100K_5%_4  [R0402]  144.66 102.37 0 top
R25303  *10K_1%_2  [R0201]  165.15 113.61 90 top
R25304  4.7K_5%_2  [R0201]  145.26 108.37 270 top
R25306  2.2_5%_6  [R0603]  169.85 109.55 90 top
R25307  *2.2_5%_6  [R0603]  148.39 106.91 90 top
R25308  33_5%_2  [R0201]  149.91 111.27 270 top
R25309  10K_1%_2  [R0201]  166.5 113.18 90 top
R25310  100K_5%_4  [R0402]  68.76 179.35 270 bottom
R25311  100K_5%_2  [R0201]  169.85 97.43 90 top
R25312  10K_5%_4  [R0402]  141.02 99.87 0 top
R25314  10K_1%_2  [R0201]  162.61 113.15 90 top
R25315  33_5%_2  [R0201]  160.93 115.34 0 top
R25316  *10K_1%_2  [R0201]  164.42 113.23 90 top
R25317  2.2_5%_6  [R0603]  146.31 105.97 180 top
R25318  33_5%_2  [R0201]  168.18 95.17 270 top
R25320  100K_5%_2  [R0201]  155.95 113.4 90 top
R25321  0_5%_4  [R0402]  11.2 155.55 0 bottom
R25322  EV@10K_1%_4  [R0402]  128.83 175.03 270 bottom
R25323  *10K_1%_2  [R0201]  149.15 111.27 90 top
R25330  *Short_4  [S0402]  169.6 115.44 270 top
R25336  *Short_8  [S0805]  94.07 103.72 0 bottom
R25343  *Short_6  [S0603]  117.35 108.66 180 bottom
R25344  0_5%_6  [R0603]  94.81 100.12 270 top
R25346  *0_5%_6  [R0603]  96.9 101.27 0 top
R25347  0_5%_6  [R0603]  94.34 96.68 270 top
R25348  *0_5%_6  [R0603]  95.87 96.68 270 top
R25357  *Short_4  [S0402]  83.54 129.5 0 top
R25358  10K_1%_2  [R0201]  111.53 108.72 180 bottom
R25359  *0_5%_4  [R0402]  115.39 110.38 90 bottom
R25362  *Short_4  [S0402]  116.36 110.38 90 bottom
R25365  *Short_4  [S0402]  83.38 191.05 180 bottom
R25366  *Short_4  [S0402]  83.52 188.74 180 bottom
R25367  10K_5%_4  [R0402]  81.27 192.37 180 bottom
R25368  10K_5%_4  [R0402]  88.36 189.36 180 bottom
R25369  100K_5%_4  [R0402]  83.49 189.76 0 bottom
R25370  *100K_5%_4  [R0402]  88.36 190.38 0 bottom
R25371  22K_5%_4  [R0402]  25.83 25.44 90 bottom
R25372  10K_5%_4  [R0402]  181.51 121.3 180 bottom
R25373  10K_5%_4  [R0402]  167.59 123.41 0 bottom
R25374  33_5%_2  [R0201]  80.84 132.36 0 top
R25375  EV@100K_1%_4  [R0402]  80.59 121.06 180 top
R25376  *EV@10K_1%_2  [R0201]  80.16 120.05 180 top
R25377  IV@1K/F_4  [R0402]  79.11 120.81 270 top
R25378  *10K_5%_4  [R0402]  108.66 114.26 180 top
R25379  *10K_5%_4  [R0402]  109.98 112.7 180 top
R25380  RS232_N@10K_5%_4  [R0402]  111.69 111.84 180 bottom
R25381  10K_5%_4  [R0402]  109.5 115.25 180 top
R25382  10K_5%_4  [R0402]  110.41 113.89 180 top
R25383  RS232_VIKI@10K_5%_4  [R0402]  117.36 111.62 270 bottom
R25384  Z8I_ZAI@10K_5%_4  [R0402]  107.07 112.58 0 bottom
R25385  Z8J@10K_5%_4  [R0402]  110.23 111.97 270 bottom
R25386  *10K_5%_4  [R0402]  87.76 115.19 0 top
R25387  LTE_N@10K_5%_4  [R0402]  95.42 120.93 0 bottom
R25388  10K_5%_4  [R0402]  85.78 115.19 0 top
R25389  LTE_P2@10K_5%_4  [R0402]  94.85 119.55 90 bottom
R25390  10K_5%_4  [R0402]  93.86 118.67 90 bottom
R25391  *TPC_N@10K_5%_4  [R0402]  93.86 120.44 90 bottom
R25392  14@10K_5%_4  [R0402]  92.87 119.61 90 bottom
R25393  NFC_P2@10K_5%_4  [R0402]  97.03 119.45 90 bottom
R25394  10K_5%_4  [R0402]  87.68 112.29 180 top
R25395  15@10K_5%_4  [R0402]  92.87 117.85 90 bottom
R25396  HDMI_R_P4@10K_5%_4  [R0402]  93.22 110.78 0 bottom
R25397  NFC_N@10K_5%_4  [R0402]  93.88 109.81 0 bottom
R25398  *10K_5%_4  [R0402]  85.78 113.56 0 top
R25399  *10K_5%_4  [R0402]  85.78 112.29 0 top
R25403  EV@100K_5%_4  [R0402]  104.85 112.9 0 top
R25413  *2.2K_5%_2  [R0201]  116.97 118.1 90 top
R25415  *2.2K_5%_2  [R0201]  117.7 118.1 90 top
R25428  10K_5%_4  [R0402]  101.71 109.92 270 top
R25429  *EV@10K_5%_4  [R0402]  104.48 110.88 270 top
R25430  EV@10K_5%_4  [R0402]  84.26 117.03 90 top
R25431  *EV@10K_5%_4  [R0402]  87.93 116.41 180 top
R25433  *10K_1%_2  [R0201]  117.32 120.62 90 top
R25434  *10K_1%_2  [R0201]  119.41 117.9 270 bottom
R25436  *20K_1%_2  [R0201]  122.26 113.85 270 bottom
R25437  10K_5%_4  [R0402]  121.23 121.89 180 top
R25438  10K_5%_4  [R0402]  120.42 123.24 180 top
R25439  10K_5%_4  [R0402]  125.02 118.64 180 top
R25440  *10K_5%_4  [R0402]  84.19 121.01 0 top
R25441  *10K_5%_4  [R0402]  84.19 119.98 0 top
R25444  *10K_5%_4  [R0402]  24.31 160.3 270 top
R25445  10K_5%_4  [R0402]  28.88 161.95 180 top
R25446  *0_5%_4  [R0402]  23.3 160.3 270 top
R25448  *Short_4  [S0402]  120.99 113.53 180 bottom
R25456  *0_5%_6  [R0603]  74.76 192.5 180 top
R25458  *Short_6  [S0603]  75.57 190.83 0 top
R25459  *Short_6  [S0603]  72.06 190.27 270 bottom
R25462  *Short_6  [S0603]  70.06 190.34 270 top
R25466  *Short_6  [S0603]  123.37 112.87 90 top
R25467  33_5%_2  [R0201]  66.48 188.49 90 top
R25468  *EV@Short_4  [S0402]  78.53 119.16 180 top
R25469  *EV@Short_4  [S0402]  124.1 208.47 90 bottom
R25471  *Short_4  [S0402]  132 105.8 90 bottom
R25472  *10K_5%_4  [R0402]  131.99 104 90 bottom
R25473  *Short_4  [S0402]  133.38 107.03 90 bottom
R25474  10K_5%_4  [R0402]  114.98 113.89 0 bottom
R25475  10K_5%_4  [R0402]  114.42 112.42 0 bottom
R25477  10K_1%_2  [R0201]  116.24 113.81 90 bottom
R25479  *Short_4  [S0402]  127.9 137.18 180 bottom
R25481  *10K_1%_2  [R0201]  118.52 119.93 90 top
R25482  *EV@10K_5%_4  [R0402]  103.47 110.86 270 top
R25487  *EV@0_5%_4  [R0402]  113.13 188.67 270 bottom
R25488  EV@80.6_1%_2  [R0201]  160.3 186.69 180 bottom
R25489  EV@80.6_1%_2  [R0201]  159.66 191.77 180 bottom
R25490  EV@10K_1%_4  [R0402]  112.1 182.17 90 top
R25492  *EV@10K_5%_4  [R0402]  118.06 178.43 90 bottom
R25493  10K_5%_4  [R0402]  88.28 118.15 270 top
R25494  *0_5%_4  [R0402]  85.19 124.98 180 top
R25495  *Short_4  [S0402]  28.63 33.8 0 bottom
R25501  10K_5%_4  [R0402]  86.46 129.61 270 top
R25517  *Short_0402  [S0402]  19.99 88.67 180 top
R25518  *Short_0402  [S0402]  19.99 87.65 180 top
R25519  2.2_5%_6  [R0603]  149.99 209.83 270 top
R25520  10K_1%_2  [R0201]  109.35 116.15 0 top
R25521  33_5%_2  [R0201]  65.46 188.49 90 top
R25522  33_5%_2  [R0201]  67.49 188.49 90 top
R25524  0_5%_4  [R0402]  139.58 99.52 270 top
R25525  HDMI_CRT_P2@100K_5%_4  [R0402]  31.17 127.27 0 top
R25526  HDMI_CRT_P2@4.7K_5%_4  [R0402]  32.54 156.64 270 top
R25527  HDMI_CRT_P2@4.7K_5%_4  [R0402]  31.52 156.64 270 top
R25528  HDMI_CRT_P2@2.2K_5%_4  [R0402]  12.67 157.35 90 top
R25529  HDMI_CRT_P2@2.2K_5%_4  [R0402]  9.27 161.05 90 top
R25530  *HDMI_CRT_P2@0_5%_4  [R0402]  32.31 148.1 90 top
R25531  *HDMI_CRT_P2@0_5%_4  [R0402]  33.33 148.1 90 top
R25532  HDMI_CRT_P2@47_5%_4  [R0402]  15.56 158.48 180 top
R25533  *HDMI_CRT_P2@4.7K_5%_4  [R0402]  33.33 145.95 270 top
R25534  HDMI_CRT_P2@100K_5%_4  [R0402]  34.47 146.07 90 top
R25535  HDMI_CRT_P2@47_5%_4  [R0402]  19.5 158.74 180 top
R25554  SM@4.7K_1%_4  [R0402]  223.7 95.02 180 top
R25555  SM@100K_1%_4  [R0402]  210.5 96.69 180 top
R25556  *SM@0_5%_4  [R0402]  210.5 94.73 180 top
R25557  *SM@0_1%_4  [R0402]  210.48 93.68 0 top
R25558  SM@470_1%_4  [R0402]  223.7 94 0 top
R25559  *SM@Short_4  [S0402]  223.7 96.03 0 top
R25560  *SM@Short_4  [S0402]  223.7 97.05 0 top
R25561  *Short_6  [S0603]  21.54 67.67 90 bottom
R25562  4.99K_1%_4  [R0402]  24.08 65.89 270 top
R25563  100K_1%_2  [R0201]  14.02 70.44 0 top
R25564  *4.7K_1%_2  [R0201]  20.12 76.1 270 top
R25565  *4.7K_1%_2  [R0201]  19.36 76.1 90 top
R25566  *4.7K_1%_2  [R0201]  17.83 76.1 270 top
R25567  *4.7K_1%_2  [R0201]  18.6 76.1 90 top
R25568  4.7K_1%_2  [R0201]  23.55 67.97 180 top
R25569  *4.7K_1%_2  [R0201]  23.55 67.21 0 top
R25570  *0_5%_6  [R0603]  23.57 68.3 0 bottom
R25571  4.7K_1%_2  [R0201]  16.2 65.12 90 top
R25572  2.2K_1%_2  [R0201]  14.72 72.57 90 top
R25573  2.2K_1%_2  [R0201]  13.95 72.57 90 top
R25574  2.2K_1%_2  [R0201]  28.14 49.43 90 bottom
R25575  2.2K_1%_2  [R0201]  26.66 49.05 90 bottom
R25576  2.2K_1%_2  [R0201]  26.66 48.03 270 bottom
R25578  100K_1%_2  [R0201]  26.58 46.8 0 bottom
R25579  0_5%_4  [R0402]  23.37 64.19 0 bottom
R25580  *2.2K_1%_2  [R0201]  17.99 54.15 0 bottom
R25589  *Short_6  [S0603]  18.72 43.84 270 bottom
R25596  *0_5%_4  [R0402]  52.6 105.5 180 top
R25597  *Short_4  [S0402]  52.54 104.47 0 top
R25598  *0_5%_4  [R0402]  55.91 130.38 180 top
R25599  *Short_4  [S0402]  53.89 104.14 270 top
R25600  *0_5%_4  [R0402]  58.26 103.53 180 top
R25601  *Short_4  [S0402]  57.26 130.56 270 top
R25602  240_1%_4  [R0402]  57.52 148.3 180 top
R25603  240_1%_4  [R0402]  65.16 149.78 180 top
R25604  240_1%_4  [R0402]  65.9 144.86 270 top
R25605  240_1%_4  [R0402]  66.9 144.86 270 top
R25606  240_1%_4  [R0402]  57.51 149.86 180 top
R25607  240_1%_4  [R0402]  65.02 147.72 180 top
R25608  240_1%_4  [R0402]  66.51 151.88 180 top
R25609  240_1%_4  [R0402]  53.92 148.57 90 top
R25610  240_1%_4  [R0402]  56.01 145.2 0 top
R25611  240_1%_4  [R0402]  65.15 148.72 180 top
R25612  1K_1%_4  [R0402]  56.57 125.75 0 top
R25614  24.9_1%_4  [R0402]  55.24 120.98 180 top
R25615  1K_1%_4  [R0402]  56.57 126.77 180 top
R25617  *Short_8  [S0805]  25.71 176.68 0 top
R25618  *2.2_1%_8  [R0805]  23.04 177.31 270 top
R25619  100K_5%_4  [R0402]  31.63 173.33 270 top
R25620  10K_5%_4  [R0402]  31.82 174.7 0 top
R25621  P4@0_5%_6  [R0603]  137.85 214.65 180 top
R25622  *P4@0_5%_6  [R0603]  134.93 216.18 180 top
R25623  *P4@0_5%_4  [R0402]  141.05 209.56 180 top
R25624  P4@0_5%_4  [R0402]  140.71 210.92 270 top
R25625  P4@0_5%_6  [R0603]  134.93 214.53 180 top
R25628  *P4@0_5%_4  [R0402]  153.06 210.4 90 bottom
R25629  *P4@4.7K_1%_4  [R0402]  106.1 177.06 270 bottom
R25630  *P4@0_1%_4  [R0402]  105.71 178.46 180 bottom
R25631  *P4@4.7K_1%_4  [R0402]  104.7 176.68 0 bottom
R25632  *P4@0_1%_4  [R0402]  102.92 176.68 180 bottom
R25633  P4@100K_1%_4  [R0402]  156.87 211.83 180 bottom
R25634  *P4@4.7K_1%_4  [R0402]  131.82 216.11 270 top
R25635  P4@4.7K_1%_4  [R0402]  157.65 214.77 270 top
R25636  P4@4.7K_1%_4  [R0402]  151.76 216.68 180 bottom
R25637  P4@0_1%_4  [R0402]  158.04 213.19 180 top
R25638  P4@0_1%_4  [R0402]  149.86 216.8 0 bottom
R25639  *P4@0_1%_4  [R0402]  130.67 216.11 270 top
R25640  *P4@100K_1%_4  [R0402]  151.32 211.82 0 bottom
R25641  P4@0_1%_4  [R0402]  150.9 210.4 90 bottom
R25642  *P4@100K_1%_4  [R0402]  151.73 215.12 180 bottom
R25643  P4@0_1%_4  [R0402]  149.83 215.12 0 bottom
R25644  *P4@100K_1%_4  [R0402]  154.37 216.23 270 bottom
R25645  P4@0_1%_4  [R0402]  151.26 212.79 0 bottom
R25646  P4@0_1%_4  [R0402]  149.33 211.6 0 bottom
R25647  *P4@100K_1%_4  [R0402]  154.08 210.43 90 bottom
R25648  *P4@100K_1%_4  [R0402]  157.66 216.56 270 top
R25650  *P4@100K_1%_4  [R0402]  151.26 214.13 180 bottom
R25652  *P4@100K_1%_4  [R0402]  147.58 211.86 0 bottom
R25667  33.2_1%_4  [R0402]  118.24 102.36 180 bottom
R67358  *HDD_R@Short_4  [S0402]  221.23 104.75 0 top
R67359  *HDD_R@Short_8  [S0805]  224.21 108.86 180 top
R67360  4.7K_5%_4  [R0402]  8.79 13.51 0 top
R67361  68.1K_1%_4  [R0402]  9.07 12.52 0 top
R67362  150K_1%_4  [R0402]  7.04 12.13 180 top
R67367  SPK_P2@0_5%_6  [R0603]  48.38 93.19 90 top
R67368  SPK_P2@0_5%_6  [R0603]  44.78 93.06 90 top
R67369  SPK_P2@0_5%_6  [R0603]  41.83 93.04 90 top
R67370  SPK_P2@0_5%_6  [R0603]  38.88 93.04 90 top
R67375  *HDMI_CRT_P2@Short_2  [R0201]  30.5 121.56 0 top
R67376  *HDMI_CRT_P2@Short_2  [R0201]  30.53 122.78 0 top
R67377  *HDMI_CRT_P2@Short_2  [R0201]  18.91 129.18 180 top
R67378  *HDMI_CRT_P2@Short_2  [R0201]  18.92 128.03 180 top
R67379  *HDMI_CRT_P2@Short_2  [R0201]  18.91 126.18 180 top
R67380  *HDMI_CRT_P2@Short_2  [R0201]  18.92 127.27 180 top
R67381  *HDMI_CRT_P2@Short_2  [R0201]  18.91 124.27 180 top
R67382  *HDMI_CRT_P2@Short_2  [R0201]  18.92 125.42 180 top
R67383  *HDMI_CRT_P2@Short_2  [R0201]  18.91 122.45 180 top
R67384  *HDMI_CRT_P2@Short_2  [R0201]  18.91 123.51 180 top
R67385  *HDMI_CRT_P2@Short_2  [R0201]  19.23 132.86 90 top
R67386  HDMI_R_P4@0_5%_4  [R0402]  22.69 146.3 90 top
R67387  HDMI_R_P4@0_5%_2  [R0201]  23.71 137.03 270 top
R67388  HDMI_R_P4@0_5%_2  [R0201]  30.95 121.56 180 top
